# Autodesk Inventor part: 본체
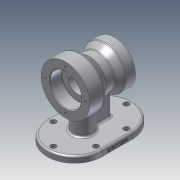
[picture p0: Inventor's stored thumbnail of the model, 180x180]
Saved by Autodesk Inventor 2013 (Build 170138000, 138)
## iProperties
Created: 2020-01
Part Number: 본체
Material: 알루미늄 6061
Document SubType Name: Modeling
Designer: user
Density: 2.71 g/cm^3
Mass: 941.582 g
Surface Area: 654.888 cm^2
Volume: 347.447 cm^3
Author: user
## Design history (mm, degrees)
sketch "스케치1"
  geometry: L1 (0, 58)-(0, -22); L2 (0, 58)-(40, 58); L3 (40, 58)-(40, 34); L4 (40, 34)-(27.5, 19.103); L5 (27.5, 19.103)-(27.5, 4.711); L6 (27.5, 4.711)-(35, -6); L7 (35, -6)-(35, -22); L8 (35, -22)-(0, -22); 1 further point
  constraints: 16 end point, 3 parallel, 2 perpendicular, 1 point on line, 1 vertical
  dimensions: "d0" = 80 distance of L1.start L1.end; "d1" = 58 distance of point (0, 0) L1.start; "d2" = 24 distance of L2.end L3.end; "d3" = 16 distance of L6.end L7.end; "d4" = 40 deg angle of L5 L4; "d5" = 35 deg angle of L5 L6; "d6" = 80 diameter of L3 L1; "d7" = 55 diameter of L5 L1; "d8" = 70 diameter of L7 L1
revolve "회전1" sketch "스케치1" stored, may be unused: angle "d9" = 90 deg
sketch "스케치2"
  geometry: C1 r 40 at (0, 0) reference; C2 r 26 at (0, 0)
  constraints: 1 centre point, 1 coincident
  dimensions: "d10" = 52 diameter of C2
extrude "돌출1" cut sketch "스케치2" distance "d11" = 20; taper "d12" = 0 deg
sketch "스케치3"
  geometry: C1 r 35 at (0, 0) reference; C2 r 20 at (0, 0)
  constraints: 1 centre point, 1 coincident
  dimensions: "d13" = 40 diameter of C2
extrude "돌출2" cut sketch "스케치3" distance "d14" = 17; taper "d15" = 0 deg
sketch "스케치4"
  geometry: C1 r 26 at (0, 0) reference; C2 r 16 at (0, 0)
  constraints: 1 centre point, 1 coincident
  dimensions: "d16" = 32 diameter of C2
extrude "돌출3" cut sketch "스케치4" stored distance "d17" = 17; taper "d18" = 0 deg
fillet "모깎기1" dims "d19" = 3, "d20" = 0.3
sketch "스케치5"
  geometry: L1 (0, 0)-(0, 33); C1 r 40 at (0, 0) reference; 1 further point
  constraints: 2 end point, 1 coincident, 1 vertical
  dimensions: "d21" = 33 distance of L1.start L1.end
hole "구멍1" sketch "스케치5" at (0, 33) diameter "d22" = 3.242; stored, may be unused: countersink angle "d26" = 90 deg, drill point angle "d28" = 118 deg; dims "d23" = 9, "d24" = 4, "d25" = 2, "d27" = 11
sketch "스케치6"
  geometry: L1 (0, 0)-(0, 27.5); C1 r 35 at (0, 0) reference; 1 further point
  constraints: 2 end point, 1 coincident, 1 vertical
  dimensions: "d32" = 27.5 distance of L1.start L1.end
hole "구멍2" sketch "스케치6" at (0, 27.5) diameter "d33" = 3.242; stored, may be unused: countersink angle "d37" = 90 deg, drill point angle "d39" = 118 deg; dims "d34" = 9, "d35" = 4, "d36" = 2, "d38" = 11
node "작업 평면1"
sketch "스케치7"
  geometry: L1 (-40, 58)-(40, 58) reference; L2 (45, 43)-(-45, 43); L3 (-45, 43)-(-45, -7); L4 (-45, -7)-(45, -7); L5 (45, -7)-(45, 43); L6 (0, 88)-(0, 43); A1 r 45 centre (0, 43) between (45, 43) and (-45, 43); A2 r 45 centre (0, -7) between (-45, -7) and (45, -7); 2 further points
  constraints: 10 end point, 5 point on circle, 3 parallel, 2 centre point, 2 midpoint, 1 coincident, 1 horizontal, 1 perpendicular, 1 vertical alignment
  dimensions: "d45" = 90 distance of L4.end L3.end; "d46" = 50 distance of L2.end L3.end; "d47" = 30 distance from line of L6.start L1
extrude "돌출4" join sketch "스케치7" distance "d48" = 10; taper "d49" = 0 deg
sketch "스케치8"
  geometry: L1 (45, -43)-(45, 7) reference; L2 (-45, 7)-(-45, -43) reference; L3 (35, 7)-(35, -43); L4 (-35, -43)-(-35, 7); A1 r 45 centre (0, -43) between (-45, -43) and (45, -43) reference; A2 r 45 centre (0, 7) between (45, 7) and (-45, 7) reference; A3 r 35 centre (0, 7) between (35, 7) and (-35, 7); A4 r 35 centre (0, -43) between (-35, -43) and (35, -43); 7 further points
  constraints: 6 point on circle, 4 coincident, 4 end point, 2 centre point, 3 other
  dimensions: "d50" = 10 distance between parallel lines of L4 L2
hole "구멍3" sketch "스케치8" at (-35, -43), (-35, 7), (0, -78), (35, -43), (35, 7), (0, 42) diameter "d51" = 9; stored, may be unused: countersink angle "d55" = 90 deg, drill point angle "d57" = 118 deg; dims "d52" = 9, "d53" = 4, "d54" = 2, "d56" = 11
sketch "스케치9" dims "d33" = 3.242
  geometry: L1 (-45, 7)-(-45, -43) reference; L2 (0, -88)-(0, -30); C1 r 16 at (0, -30); A1 r 45 centre (0, -43) between (-45, -43) and (45, -43) reference; 1 further point
  constraints: 2 end point, 1 centre point, 1 coincident, 1 parallel, 1 point on circle
  dimensions: "d58" = 58 distance of L2.start L2.end; "d59" = 32 diameter of C1
extrude "돌출5" join sketch "스케치9" stored distance "d60" = 10; taper "d61" = 0 deg
sketch "스케치10"
  geometry: L1 (35, -6.946)-(35, -22) reference; L2 (35, -22)-(29.121, -22) reference; L3 (29.121, -22)-(29.121, -11) reference; L4 (29.121, -11)-(27.5, -10.026) reference; L5 (27.5, -10.026)-(25.879, -11) reference; L6 (25.879, -11)-(25.879, -22) reference; L7 (25.879, -22)-(20, -22) reference; L8 (20, -22)-(20, -5.3) reference; L9 (19.7, -5)-(16, -5) reference; L10 (16, -5)-(16, 38) reference; L11 (16, 38)-(25.7, 38) reference; L12 (26, 38.3)-(26, 58) reference; L13 (26, 58)-(31.379, 58) reference; L14 (31.379, 58)-(31.379, 47) reference; L15 (31.379, 47)-(33, 46.026) reference; L16 (33, 46.026)-(34.621, 47) reference; L17 (34.621, 47)-(34.621, 58) reference; L18 (34.621, 58)-(40, 58) reference; L19 (40, 58)-(40, 35.092) reference; L20 (39.298, 33.164)-(28.202, 19.94) reference; L21 (27.5, 18.011)-(27.5, 5.657) reference; L22 (28.043, 3.936)-(34.457, -5.225) reference; L23 (-70, -37.5)-(-80, -37.5) reference; L24 (-80, -37.5)-(-80, 73.5) reference; L25 (-80, 73.5)-(-70, 73.5) reference; L26 (-70, 73.5)-(-70, 46) reference; L27 (-70, 46)-(-40, 46) reference; L28 (-40, 46)-(-40, 58) reference; L29 (-40, 58)-(-34.621, 58) reference; L30 (-34.621, 58)-(-34.621, 47) reference; L31 (-34.621, 47)-(-33, 46.026) reference; L32 (-33, 46.026)-(-31.379, 47) reference; L33 (-31.379, 47)-(-31.379, 58) reference; L34 (-31.379, 58)-(-26, 58) reference; L35 (-26, 58)-(-26, 38.3) reference; L36 (-25.7, 38)-(-16, 38) reference; L37 (-16, 38)-(-16, -5) reference; L38 (-16, -5)-(-19.7, -5) reference; L39 (-20, -5.3)-(-20, -22) reference; L40 (-20, -22)-(-25.879, -22) reference; L41 (-25.879, -22)-(-25.879, -11) reference; L42 (-25.879, -11)-(-27.5, -10.026) reference; L43 (-27.5, -10.026)-(-29.121, -11) reference; L44 (-29.121, -11)-(-29.121, -22) reference; L45 (-29.121, -22)-(-35, -22) reference; L46 (-35, -22)-(-35, -6.946) reference; L47 (-34.457, -5.225)-(-28.043, 3.936) reference; L48 (-27.5, 5.657)-(-27.5, 14) reference; L49 (-27.5, 14)-(-70, 14) reference; L50 (-70, 14)-(-70, -37.5) reference; L51 (-70, -52)-(-80, -52) reference; L52 (-80, -52)-(-80, -46.5) reference; L53 (-80, -46.5)-(-70, -46.5) reference; L54 (-70, -46.5)-(-70, -52) reference; L55 (-80, 88)-(-70, 88) reference; L56 (-70, 88)-(-70, 82.5) reference; L57 (-70, 82.5)-(-80, 82.5) reference; L58 (-80, 82.5)-(-80, 88) reference; L59 (-35, -12)-(-70, -12); A1 r 3 centre (32, -6.946) between (35, -6.946) and (34.457, -5.225) reference; A2 r 0.3 centre (19.7, -5.3) between (20, -5.3) and (19.7, -5) reference; A3 r 0.3 centre (25.7, 38.3) between (25.7, 38) and (26, 38.3) reference; A4 r 3 centre (37, 35.092) between (39.298, 33.164) and (40, 35.092) reference; A5 r 3 centre (30.5, 18.011) between (28.202, 19.94) and (27.5, 18.011) reference; A6 r 3 centre (30.5, 5.657) between (27.5, 5.657) and (28.043, 3.936) reference; A7 r 0.3 centre (-25.7, 38.3) between (-26, 38.3) and (-25.7, 38) reference; A8 r 0.3 centre (-19.7, -5.3) between (-19.7, -5) and (-20, -5.3) reference; A9 r 3 centre (-32, -6.946) between (-34.457, -5.225) and (-35, -6.946) reference; A10 r 3 centre (-30.5, 5.657) between (-28.043, 3.936) and (-27.5, 5.657) reference; 1 further point
  constraints: 2 end point, 2 point on line, 1 perpendicular
  dimensions: "d62" = 10 distance between parallel lines of L59 L45
feature "리브1" sketch "스케치10" dims "d63" = 1, "d64" = 10, "d65" = 0, "d66" = 0, "d67" = 1, "d68" = 1
fillet "모깎기2" dims "d69" = 3
fillet "모깎기3" dims "d70" = 3
chamfer "모따기1" distance "d71" = 1; stored, may be unused: second distance "d72" = 2, angle "d73" = 45 deg
sketch "스케치11"
  geometry: L1 (95, 0)-(50, 0) reference; L2 (0, 7)-(50, 7) reference; L3 (50, 0)-(50, 7) reference; L4 (50, 0)-(0, 0) reference; L5 (0, 0)-(0, 7) reference; L6 (-45, 0)-(-45, 7) reference; 2 further points
  constraints: 1 other
  dimensions: "d74" = 4 distance from line of L1 point (25, 4); "d75" = 70 horizontal distance of point (25, 4) L6.start
feature "엠보싱1" sketch "스케치11" dims "d0" = 80, "d1" = 58, "d2" = 24, "d3" = 16, "d4" = 40 deg, "d5" = 35 deg, "d6" = 80, "d7" = 55, "d8" = 70, "d76" = 0.5, "d77" = 0
node "솔리드1"
pattern_circular "원형 패턴1" dims angle "d30" = 360 deg
pattern_circular "원형 패턴2" dims angle "d41" = 360 deg
node "절단 모서리 투영1"
node "절단 모서리 투영2"
